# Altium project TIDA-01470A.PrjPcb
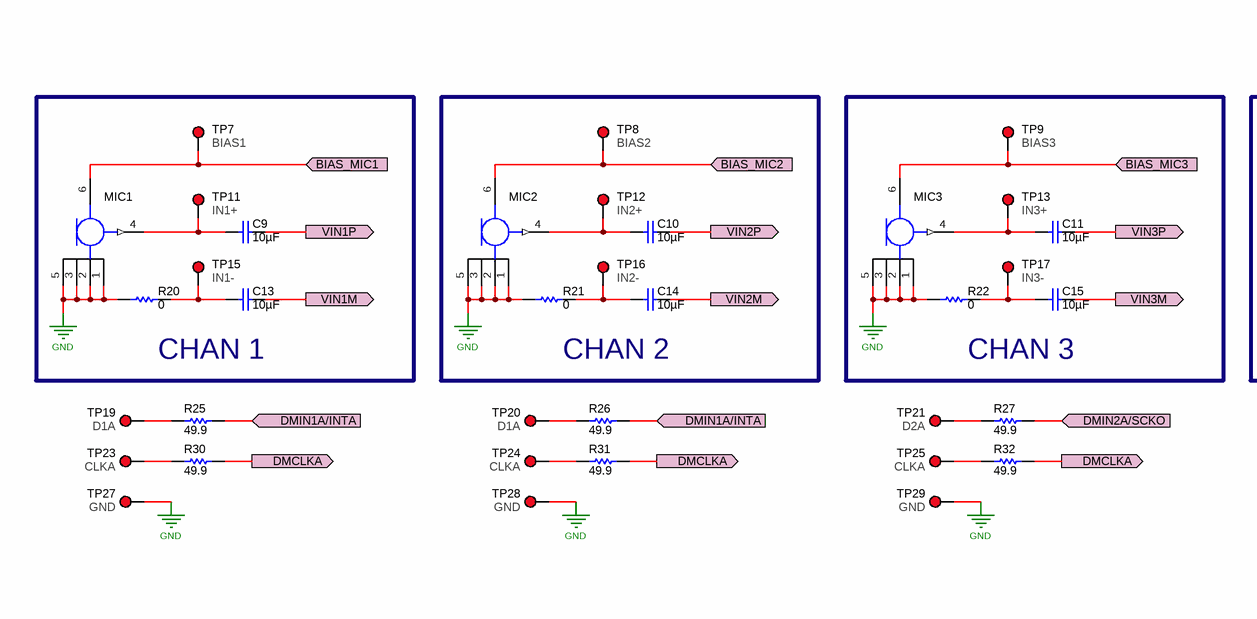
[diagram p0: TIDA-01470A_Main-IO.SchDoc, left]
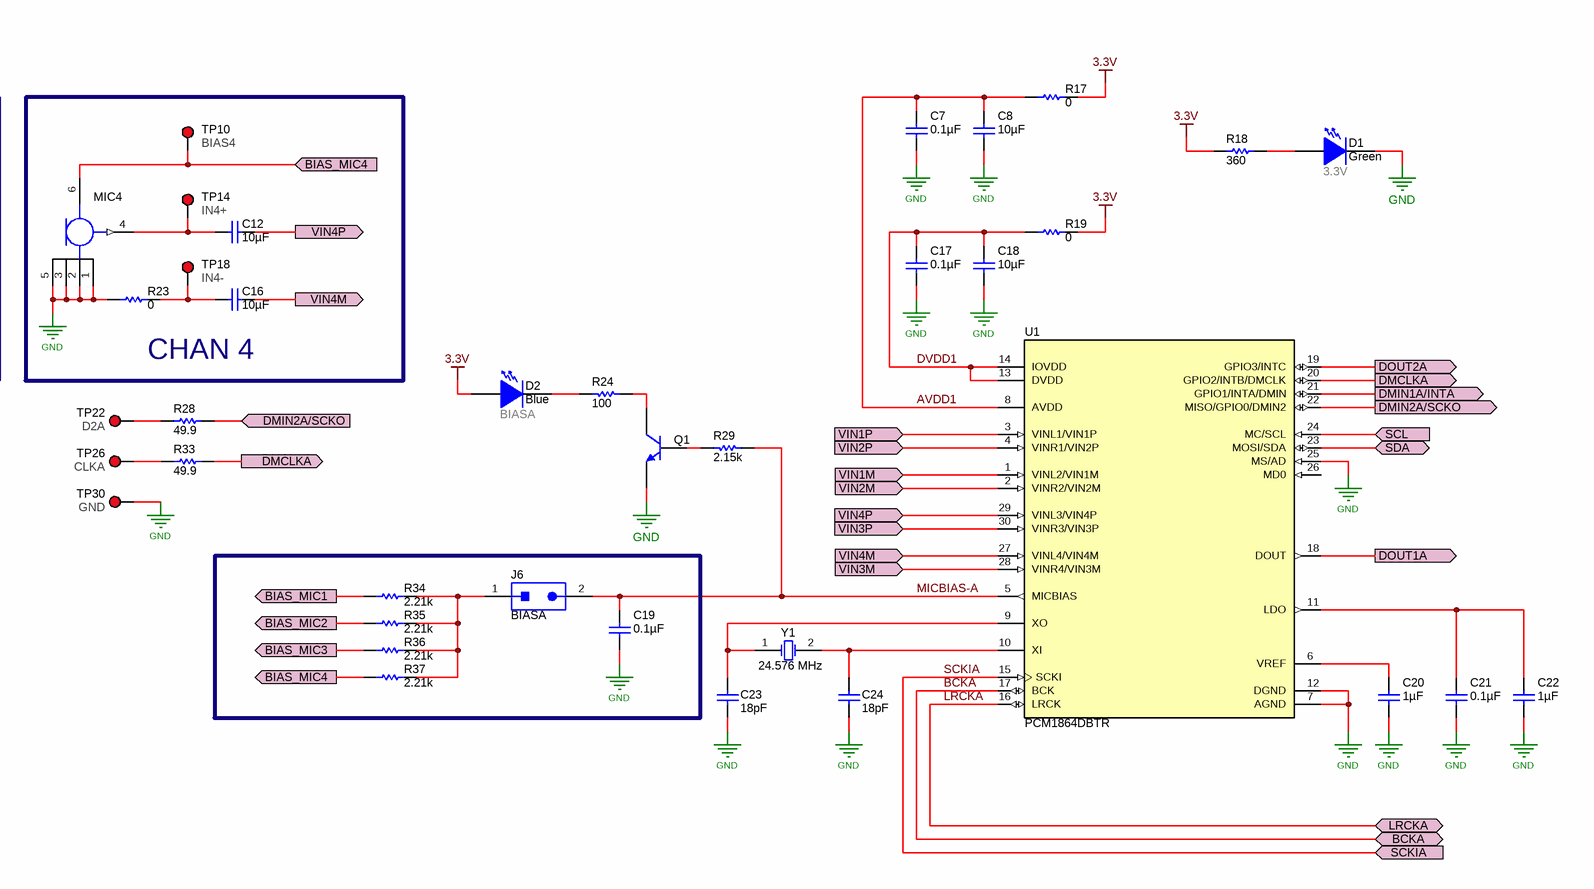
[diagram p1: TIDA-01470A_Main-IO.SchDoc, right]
CopyrightYear: 2017; EVM_Orderable: PCM1864LMBEVM; PCB_Layout: LDN; PCB_Rev: A; PRJ_Customer: Public Release; PRJ_Engineer: Ravi Patil; PRJ_Number: TIDA-01470; PRJ_Title: PCM1864 Linear Microphone Board Reference Design; SCH_Rev: A; TechSupport: http://www.ti.com/support; TID: 01470
3 sheets, 133 parts. Net scope: flat (ports and power ports of the same name join across sheets).
Board file: TIDA-01470A-PCB.PcbDoc
Sheets:
  TIDA-01470A_Main-IO.SchDoc
  TIDA-01470A_DIG-IO.SchDoc
  TIDA-01470A_Hardware.SchDoc

## Sheet TIDA-01470A_Main-IO.SchDoc: Main I/O
size 538 x 342 mm; Date: Not shown in title block; ApprovedBy: Not shown in title block; CheckedBy: Not shown in title block; Author: Not shown in title block; CompanyName: Not shown in title block; DrawnBy: LDN; Engineer: Not shown in title block; Organization: Not shown in title block; Address1: Not shown in title block; Address2: Not shown in title block; Address3: Not shown in title block; Address4: Not shown in title block; DocumentNumber: 1; Revision: Use project parameter SCH_Rev; SheetNumber: 1; SheetTotal: 3; PageSetup: Record=PageOptions¦CenterHorizontal=True¦CenterVertical=True¦PrintScale=1.00¦XCorrection=1.00¦YCorrection=1.00¦PrintKind=0¦BorderSize=5000000¦LeftOffset=0¦BottomOffset=0¦Orientation=2¦PaperLength=1000¦PaperWidth=1000¦Scale=100¦PaperSource=15¦PrintQuality=600¦MediaType=1¦DitherType=10¦PaperKind=Letter¦PrintScaleMode=1

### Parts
C7  ValueDisplayed: 0.1µF  [0603L]  (hidden comment: GRM188R71C104KA01D)
C8  ValueDisplayed: 10µF  [0805_KTR]  (hidden comment: GRM21BR71A106KE51K)
C9  ValueDisplayed: 10µF  [0805_KTR]  (hidden comment: GRM21BR71A106KE51K)
C10  ValueDisplayed: 10µF  [0805_KTR]  (hidden comment: GRM21BR71A106KE51K)
C11  ValueDisplayed: 10µF  [0805_KTR]  (hidden comment: GRM21BR71A106KE51K)
C12  ValueDisplayed: 10µF  [0805_KTR]  (hidden comment: GRM21BR71A106KE51K)
C13  ValueDisplayed: 10µF  [0805_KTR]  (hidden comment: GRM21BR71A106KE51K)
C14  ValueDisplayed: 10µF  [0805_KTR]  (hidden comment: GRM21BR71A106KE51K)
C15  ValueDisplayed: 10µF  [0805_KTR]  (hidden comment: GRM21BR71A106KE51K)
C16  ValueDisplayed: 10µF  [0805_KTR]  (hidden comment: GRM21BR71A106KE51K)
C17  ValueDisplayed: 0.1µF  [0603L]  (hidden comment: GRM188R71C104KA01D)
C18  ValueDisplayed: 10µF  [0805_KTR]  (hidden comment: GRM21BR71A106KE51K)
C19  ValueDisplayed: 0.1µF  [0603L]  (hidden comment: GRM188R71C104KA01D)
C20  ValueDisplayed: 1µF  [0603L]  (hidden comment: GRM188R71C105KA12D)
C21  ValueDisplayed: 0.1µF  [0603L]  (hidden comment: GRM188R71C104KA01D)
C22  ValueDisplayed: 1µF  [0603L]  (hidden comment: GRM188R71C105KA12D)
C23  ValueDisplayed: 18pF  [0603L]  (hidden comment: GRM1885C1H180JA01D)
C24  ValueDisplayed: 18pF  [0603L]  (hidden comment: GRM1885C1H180JA01D)
D1  3.3V  value Green  [LED_LTST-C171]
D2  BIASA  value Blue  [LED_SMLP12_BLUE]
J6  BIASA  [Sullins_PBC02SAAN]
MIC1  SPH1642HT5H-1  [Knowles_SPH1642HT5H-1]  (value not drawn)
MIC2  SPH1642HT5H-1  [Knowles_SPH1642HT5H-1]  (value not drawn)
MIC3  SPH1642HT5H-1  [Knowles_SPH1642HT5H-1]  (value not drawn)
MIC4  SPH1642HT5H-1  [Knowles_SPH1642HT5H-1]  (value not drawn)
Q1  MMBT2222A  [SOT-23]  (value not drawn)
R17  ValueDisplayed: 0  [0603]  (hidden comment: CRCW06030000Z0EA)
R18  value 360  [0402L]  (hidden comment: CRCW0402360RJNED)
R19  ValueDisplayed: 0  [0603L]  (hidden comment: CRCW06030000Z0EA)
R20  ValueDisplayed: 0  [0603L]  (hidden comment: CRCW06030000Z0EA)
R21  ValueDisplayed: 0  [0603L]  (hidden comment: CRCW06030000Z0EA)
R22  ValueDisplayed: 0  [0603L]  (hidden comment: CRCW06030000Z0EA)
R23  ValueDisplayed: 0  [0603L]  (hidden comment: CRCW06030000Z0EA)
R24  ValueDisplayed: 100  [0402L]  (hidden comment: ERJ-2RKF1000X)
R25  ValueDisplayed: 49.9  [0402L]  (hidden comment: RC0402FR-0749R9L)
R26  ValueDisplayed: 49.9  [0402L]  (hidden comment: RC0402FR-0749R9L)
R27  ValueDisplayed: 49.9  [0402L]  (hidden comment: RC0402FR-0749R9L)
R28  ValueDisplayed: 49.9  [0402L]  (hidden comment: RC0402FR-0749R9L)
R29  ValueDisplayed: 2.15k  [0402L]  (hidden comment: CRCW04022K15FKED)
R30  ValueDisplayed: 49.9  [0402L]  (hidden comment: RC0402FR-0749R9L)
R31  ValueDisplayed: 49.9  [0402L]  (hidden comment: RC0402FR-0749R9L)
R32  ValueDisplayed: 49.9  [0402L]  (hidden comment: RC0402FR-0749R9L)
R33  ValueDisplayed: 49.9  [0402L]  (hidden comment: RC0402FR-0749R9L)
R34  ValueDisplayed: 2.21k  [0402L]  (hidden comment: CRCW04022K21FKED)
R35  ValueDisplayed: 2.21k  [0402L]  (hidden comment: CRCW04022K21FKED)
R36  ValueDisplayed: 2.21k  [0402L]  (hidden comment: CRCW04022K21FKED)
R37  ValueDisplayed: 2.21k  [0402L]  (hidden comment: CRCW04022K21FKED)
TP7  BIAS1  [TestPoint_50x30-TH]
TP8  BIAS2  [TestPoint_50x30-TH]
TP9  BIAS3  [TestPoint_50x30-TH]
TP10  BIAS4  [TestPoint_50x30-TH]
TP11  IN1+  [TestPoint_50x30-TH]
TP12  IN2+  [TestPoint_50x30-TH]
TP13  IN3+  [TestPoint_50x30-TH]
TP14  IN4+  [TestPoint_50x30-TH]
TP15  IN1-  [TestPoint_50x30-TH]
TP16  IN2-  [TestPoint_50x30-TH]
TP17  IN3-  [TestPoint_50x30-TH]
TP18  IN4-  [TestPoint_50x30-TH]
TP19  D1A  [TestPoint_50x30-TH]
TP20  D1A  [TestPoint_50x30-TH]
TP21  D2A  [TestPoint_50x30-TH]
TP22  D2A  [TestPoint_50x30-TH]
TP23  CLKA  [TestPoint_50x30-TH]
TP24  CLKA  [TestPoint_50x30-TH]
TP25  CLKA  [TestPoint_50x30-TH]
TP26  CLKA  [TestPoint_50x30-TH]
TP27  GND  [TestPoint_50x30-TH]
TP28  GND  [TestPoint_50x30-TH]
TP29  GND  [TestPoint_50x30-TH]
TP30  GND  [TestPoint_50x30-TH]
U1  PCM1864DBTR  [DBT0030A_N]
Y1  Frequency: 24.576 MHz  [TXC_9B]  (hidden comment: 9B-24.576MEEJ-B)

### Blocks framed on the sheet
CHAN 1: C9 C13 MIC1 R20 TP7 TP11 TP15
CHAN 2: C10 C14 MIC2 R21 TP8 TP12 TP16
CHAN 3: C11 C15 MIC3 R22 TP9 TP13 TP17
CHAN 4: C12 C16 MIC4 R23 TP10 TP14 TP18

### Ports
BCKA (bidir), BIAS_MIC1 (in), BIAS_MIC1 (out), BIAS_MIC2 (in), BIAS_MIC2 (out), BIAS_MIC3 (in), BIAS_MIC3 (out), BIAS_MIC4 (in), BIAS_MIC4 (out), DMCLKA (out), DMIN1A/INTA (in), DMIN1A/INTA (out), DMIN2A/SCKO (in), DMIN2A/SCKO (out), DOUT1A (out), DOUT2A (out), LRCKA (bidir), SCKIA (in), SCL (in), SDA (bidir), VIN1M (in), VIN1M (out), VIN1P (in), VIN1P (out), VIN2M (in), VIN2M (out), VIN2P (in), VIN2P (out), VIN3M (in), VIN3M (out), VIN3P (in), VIN3P (out), VIN4M (in), VIN4M (out), VIN4P (in), VIN4P (out)

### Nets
3.3V: D2.1(A) R17.1 R18.2 R19.1
GND: C7.1 C8.1 C17.1 C18.1 C19.1 C20.2 C21.1 C22.2 C23.2 C24.2 D1.2(K) MIC1.1(GND) MIC1.2(GND) MIC1.3(GND) MIC1.5(GND) MIC2.1(GND) MIC2.2(GND) MIC2.3(GND) MIC2.5(GND) MIC3.1(GND) MIC3.2(GND) MIC3.3(GND) MIC3.5(GND) MIC4.1(GND) MIC4.2(GND) MIC4.3(GND) MIC4.5(GND) Q1.2(E) R20.2 R21.2 R22.2 R23.2 TP27.1 TP28.1 TP29.1 TP30.1 U1.7(AGND) U1.12(DGND) U1.25(MS/AD)
AVDD1: C7.2 C8.2 R17.2 U1.8(AVDD)
BCKA: U1.17(BCK) ; port BCKA
BIAS_MIC1: MIC1.6(VDD) R34.2 TP7.1 ; port BIAS_MIC1
BIAS_MIC2: MIC2.6(VDD) R35.2 TP8.1 ; port BIAS_MIC2
BIAS_MIC3: MIC3.6(VDD) R36.2 TP9.1 ; port BIAS_MIC3
BIAS_MIC4: MIC4.6(VDD) R37.2 TP10.1 ; port BIAS_MIC4
DMCLKA: R30.1 R31.1 R32.1 R33.1 U1.20(GPIO2/INTB/DMCLK) ; port DMCLKA
DMIN1A/INTA: R25.1 R26.1 U1.21(GPIO1/INTA/DMIN) ; port DMIN1A/INTA
DMIN2A/SCKO: R27.1 R28.1 U1.22(MISO/GPIO0/DMIN2) ; port DMIN2A/SCKO
DOUT1A: U1.18(DOUT) ; port DOUT1A
DOUT2A: U1.19(GPIO3/INTC) ; port DOUT2A
DVDD1: C17.2 C18.2 R19.2 U1.13(DVDD) U1.14(IOVDD)
LRCKA: U1.16(LRCK) ; port LRCKA
MICBIAS-A: C19.2 J6.2 R29.2 U1.5(MICBIAS)
SCKIA: U1.15(SCKI) ; port SCKIA
SCL: U1.24(MC/SCL) ; port SCL
SDA: U1.23(MOSI/SDA) ; port SDA
VIN1M: C13.1 U1.1(VINL2/VIN1M) ; port VIN1M
VIN1P: C9.1 U1.3(VINL1/VIN1P) ; port VIN1P
VIN2M: C14.1 U1.2(VINR2/VIN2M) ; port VIN2M
VIN2P: C10.1 U1.4(VINR1/VIN2P) ; port VIN2P
VIN3M: C15.1 U1.28(VINR4/VIN3M) ; port VIN3M
VIN3P: C11.1 U1.30(VINR3/VIN3P) ; port VIN3P
VIN4M: C16.1 U1.27(VINL4/VIN4M) ; port VIN4M
VIN4P: C12.1 U1.29(VINL3/VIN4P) ; port VIN4P
NetC9_2: C9.2 MIC1.4(OUTPUT) TP11.1
NetC10_2: C10.2 MIC2.4(OUTPUT) TP12.1
NetC11_2: C11.2 MIC3.4(OUTPUT) TP13.1
NetC12_2: C12.2 MIC4.4(OUTPUT) TP14.1
NetC13_2: C13.2 R20.1 TP15.1
NetC14_2: C14.2 R21.1 TP16.1
NetC15_2: C15.2 R22.1 TP17.1
NetC16_2: C16.2 R23.1 TP18.1
NetC20_1: C20.1 U1.6(VREF)
NetC21_2: C21.2 C22.1 U1.11(LDO)
NetC23_1: C23.1 U1.9(XO) Y1.1(OSC1)
NetC24_1: C24.1 U1.10(XI) Y1.2(OSC2)
NetD1_1: D1.1(A) R18.1
NetD2_2: D2.2(K) R24.1
NetJ6_1: J6.1 R34.1 R35.1 R36.1 R37.1
NetQ1_1: Q1.1(B) R29.1
NetQ1_3: Q1.3(C) R24.2
NetR25_2: R25.2 TP19.1
NetR26_2: R26.2 TP20.1
NetR27_2: R27.2 TP21.1
NetR28_2: R28.2 TP22.1
NetR30_2: R30.2 TP23.1
NetR31_2: R31.2 TP24.1
NetR32_2: R32.2 TP25.1
NetR33_2: R33.2 TP26.1

Not connected (* = marked no-connect by the designer): U1 26(MD0)

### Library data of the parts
C7 C17 C19 C21 = GRM188R71C104KA01D: CAP, CERM, 0.1 µF, 16 V, +/- 10%, X7R, 0603; Manufacturer: MuRata; Polarized: N; CompType: Capacitor; Value: 0.1uF; U/M: EA; Cap_F: 0.0000001; Tolerance_%: 10; Value1: Unknown; VDC_V: 16; Value2: 16V; TaMin_C: -55; TaMax_C: 125; Cap_Case: 0603; SizeArea_mm2: 1.28; SizeAreaWB_mm2: 4.68; SizeX_mm: 1.6; SizeY_mm: 0.8; SizeZ_mm: 1; AEC Category: Q200
C8-C16 C18 = GRM21BR71A106KE51K: CAP, CERM, 10 µF, 10 V, +/- 10%, X7R, 0805; Manufacturer: MuRata; Polarized: N; CompType: Capacitor; Value: 10uF; U/M: EA; Cap_F: 0.00001; Tolerance_%: 10; Value1: Unknown; Value2: 10V; TaMin_C: -55; TaMax_C: 125; Cap_Case: 0805; SizeArea_mm2: 2.5; SizeAreaWB_mm2: 6.75; SizeX_mm: 2; SizeY_mm: 1.25; SizeZ_mm: 1.45; AEC Category: Q200
C20 C22 = GRM188R71C105KA12D: CAP, CERM, 1 µF, 16 V, +/- 10%, X7R, 0603; Manufacturer: MuRata; Polarized: N; CompType: Capacitor; Value: 1uF; U/M: EA; Cap_F: 0.000001; Tolerance_%: 10; ESR_ohm: 0.011; Value1: 0.011 ohm; VDC_V: 16; Value2: 16V; TaMin_C: -55; TaMax_C: 125; Cap_Case: 0603; SizeArea_mm2: 1.28; SizeAreaWB_mm2: 4.68; SizeX_mm: 1.6; SizeY_mm: 0.8; SizeZ_mm: 1; AEC Category: Q200
C23 C24 = GRM1885C1H180JA01D: CAP, CERM, 18 pF, 50 V, +/- 5%, C0G/NP0, 0603; Manufacturer: MuRata; Polarized: N; CompType: Capacitor; Value: 18pF; U/M: EA; Cap_F: 0.000000000018; Tolerance_%: 5; Value1: Unknown; VDC_V: 50; Value2: 50V; TaMin_C: -55; TaMax_C: 125; Cap_Case: 0603; SizeArea_mm2: 1.28; SizeAreaWB_mm2: 4.68; SizeX_mm: 1.6; SizeY_mm: 0.8; SizeZ_mm: 1; AEC Category: Q200
D1 = LTST-C171GKT: LED, Green, SMD; Manufacturer: Lite-On; Type: AlInGaP; Vf_V: 2.1; Value2: 2.1V; Io_A: 20; Value1: W; U/M: EA
D2 = SMLP12BC7TT86: LED, Blue, SMD; Manufacturer: Rohm; Type: InGaN; Vf_V: 2.9; Value2: 2.9V; Io_A: 0.005; Tjmax_C: 85; Value1: W; U/M: EA
J6 = PBC02SAAN: Header, 100mil, 2x1, Gold, TH; Manufacturer: Sullins Connector Solutions; SymbolCreator: a0412235; Pitch_mm: 2.54; Gender: Male; Shrouded: N; Row_Count: 1; Current_A: 3; Voltage_V: 1800; Cert_UL: Y
MIC1-MIC4 = SPH1642HT5H-1: Wide Bandwidth, Low Noise, Precision Top Port SiSonic Microphone, SMD; Manufacturer: Knowles Accoustics; SymbolCreator: Altium
Q1 = MMBT2222A, Fairchild Semiconductor: Transistor, NPN, 40 V, 0.15 A, SOT-23; CompType: BJT; PNP: 0; NPN: 1; Vceo_V: 40; Vcesat1_V: 0.3; Value: 40 V; IcRated_A: 0.15; Value1: 0.15 A; HfeMax: 300; TaMin_C: -55; TaMax_C: 150; U/M: EA; AEC Category: Q101
R17 R19-R23 = CRCW06030000Z0EA: RES, 0, 5%, 0.1 W, 0603; Manufacturer: Vishay-Dale; CompType: Resistor; Value: 0; Value_Code: 0000; Tolerance_%: 5; Power_W: 0.1; Value2: 0.1W; VDC_V: 75; TempCo: 200 ppm/C; SizeArea_mm2: 1.28; SizeX_mm: 1.6; SizeY_mm: 0.8; SizeZ_mm: 1; EIA_Code: E24; U/M: EA; AEC Category: Q200
R18 = CRCW0402360RJNED: RES, 360, 5%, 0.063 W, 0402; Manufacturer: Vishay-Dale; CompType: Resistor; Value_Code: 360R; Tolerance_%: 5; Power_W: 0.063; Value2: 0.063W; VDC_V: 50; TempCo: 200 ppm/C; EIA_Code: E24; U/M: EA; AEC Category: Q200
R24 = ERJ-2RKF1000X: RES, 100, 1%, 0.1 W, 0402; Manufacturer: Panasonic; CompType: Resistor; Value: 100; Value_Code: 100R; Tolerance_%: 1; Power_W: 0.1; Value2: 0.1W; VDC_V: 50; TempCo: 100 ppm/C; EIA_Code: E96; U/M: EA; AEC Category: Q200; SizeArea_mm2: 0.5; SizeZ_mm: 0.6
R25-R28 R30-R33 = RC0402FR-0749R9L: RES, 49.9, 1%, 0.063 W, 0402; Manufacturer: Yageo America; CompType: Resistor; Value: 49.9; Value_Code: 49R9; Tolerance_%: 1; Power_W: 0.063; Value2: 0.063W; VDC_V: 50; TempCo: 100 ppm/C; SizeArea_mm2: 0.5; SizeZ_mm: 0.6; EIA_Code: E96; U/M: EA; AEC Category: Q200; AEC Qualified: N
R29 = CRCW04022K15FKED: RES, 2.15 k, 1%, 0.063 W, 0402; Manufacturer: Vishay-Dale; CompType: Resistor; Value: 2.15k; Res_ohm: 2150; Value_Code: 2k15; Tolerance_%: 1; Power_W: 0.063; Value2: 0.063W; VDC_V: 50; TempCo: 100 ppm/C; EIA_Code: E96; U/M: EA; AEC Category: Q200; SizeArea_mm2: 0.5; SizeZ_mm: 0.6
R34-R37 = CRCW04022K21FKED: RES, 2.21 k, 1%, 0.063 W, 0402; Manufacturer: Vishay-Dale; CompType: Resistor; Value: 2.21k; Res_ohm: 2210; Value_Code: 2k21; Tolerance_%: 1; Power_W: 0.063; Value2: 0.063W; VDC_V: 50; TempCo: 100 ppm/C; SizeArea_mm2: 0.5; SizeZ_mm: 0.6; EIA_Code: E96; U/M: EA; AEC Category: Q200
TP7-TP30 = 5000: Test Point, Miniature, Red, TH; Manufacturer: Keystone; CompType: Test Point Loop; ContactFinish: Silver
U1 = PCM1864DBTR: Universal Microphone to 2VRMS Analog input, 24-Bit, 192 kHz Stereo Front-End, DBT0030A; Manufacturer: Texas Instruments; SymbolCreator: Altium; SizeArea_mm2: 49.92; SizeAreaWB_mm2: 82.32; SizeX_mm: 6.4; SizeY_mm: 7.8; SizeZ_mm: 1.2; CompType: IC; U/M: EA
Y1 = 9B-24.576MEEJ-B: Crystal, 24.576MHz, 18 pF, TH; Manufacturer: TXC Corporation; SymbolCreator: a0412235; SizeAreaWB_mm2: 94.5; SizeArea_mm2: 57.5; SizeX_mm: 11.5; SizeY_mm: 5; SizeZ_mm: 3.68; U/M: EA; TaMin_C: -20; TaMax_C: 70; Frequency Stability: ±10ppm

## Sheet TIDA-01470A_DIG-IO.SchDoc: DIGITAL I/O
size 431 x 279 mm; Date: Not shown in title block; ApprovedBy: Not shown in title block; CheckedBy: Not shown in title block; Author: Not shown in title block; CompanyName: Not shown in title block; DrawnBy: LDN; Engineer: Not shown in title block; Organization: Not shown in title block; Address1: Not shown in title block; Address2: Not shown in title block; Address3: Not shown in title block; Address4: Not shown in title block; DocumentNumber: 2; Revision: Use project parameter SCH_Rev; SheetNumber: 2; SheetTotal: 3; PageSetup: Record=PageOptions¦CenterHorizontal=True¦CenterVertical=True¦PrintScale=1.00¦XCorrection=1.00¦YCorrection=1.00¦PrintKind=0¦BorderSize=5000000¦LeftOffset=0¦BottomOffset=0¦Orientation=2¦PaperLength=1000¦PaperWidth=1000¦Scale=100¦PaperSource=15¦PrintQuality=600¦MediaType=1¦DitherType=10¦PaperKind=Letter¦PrintScaleMode=1
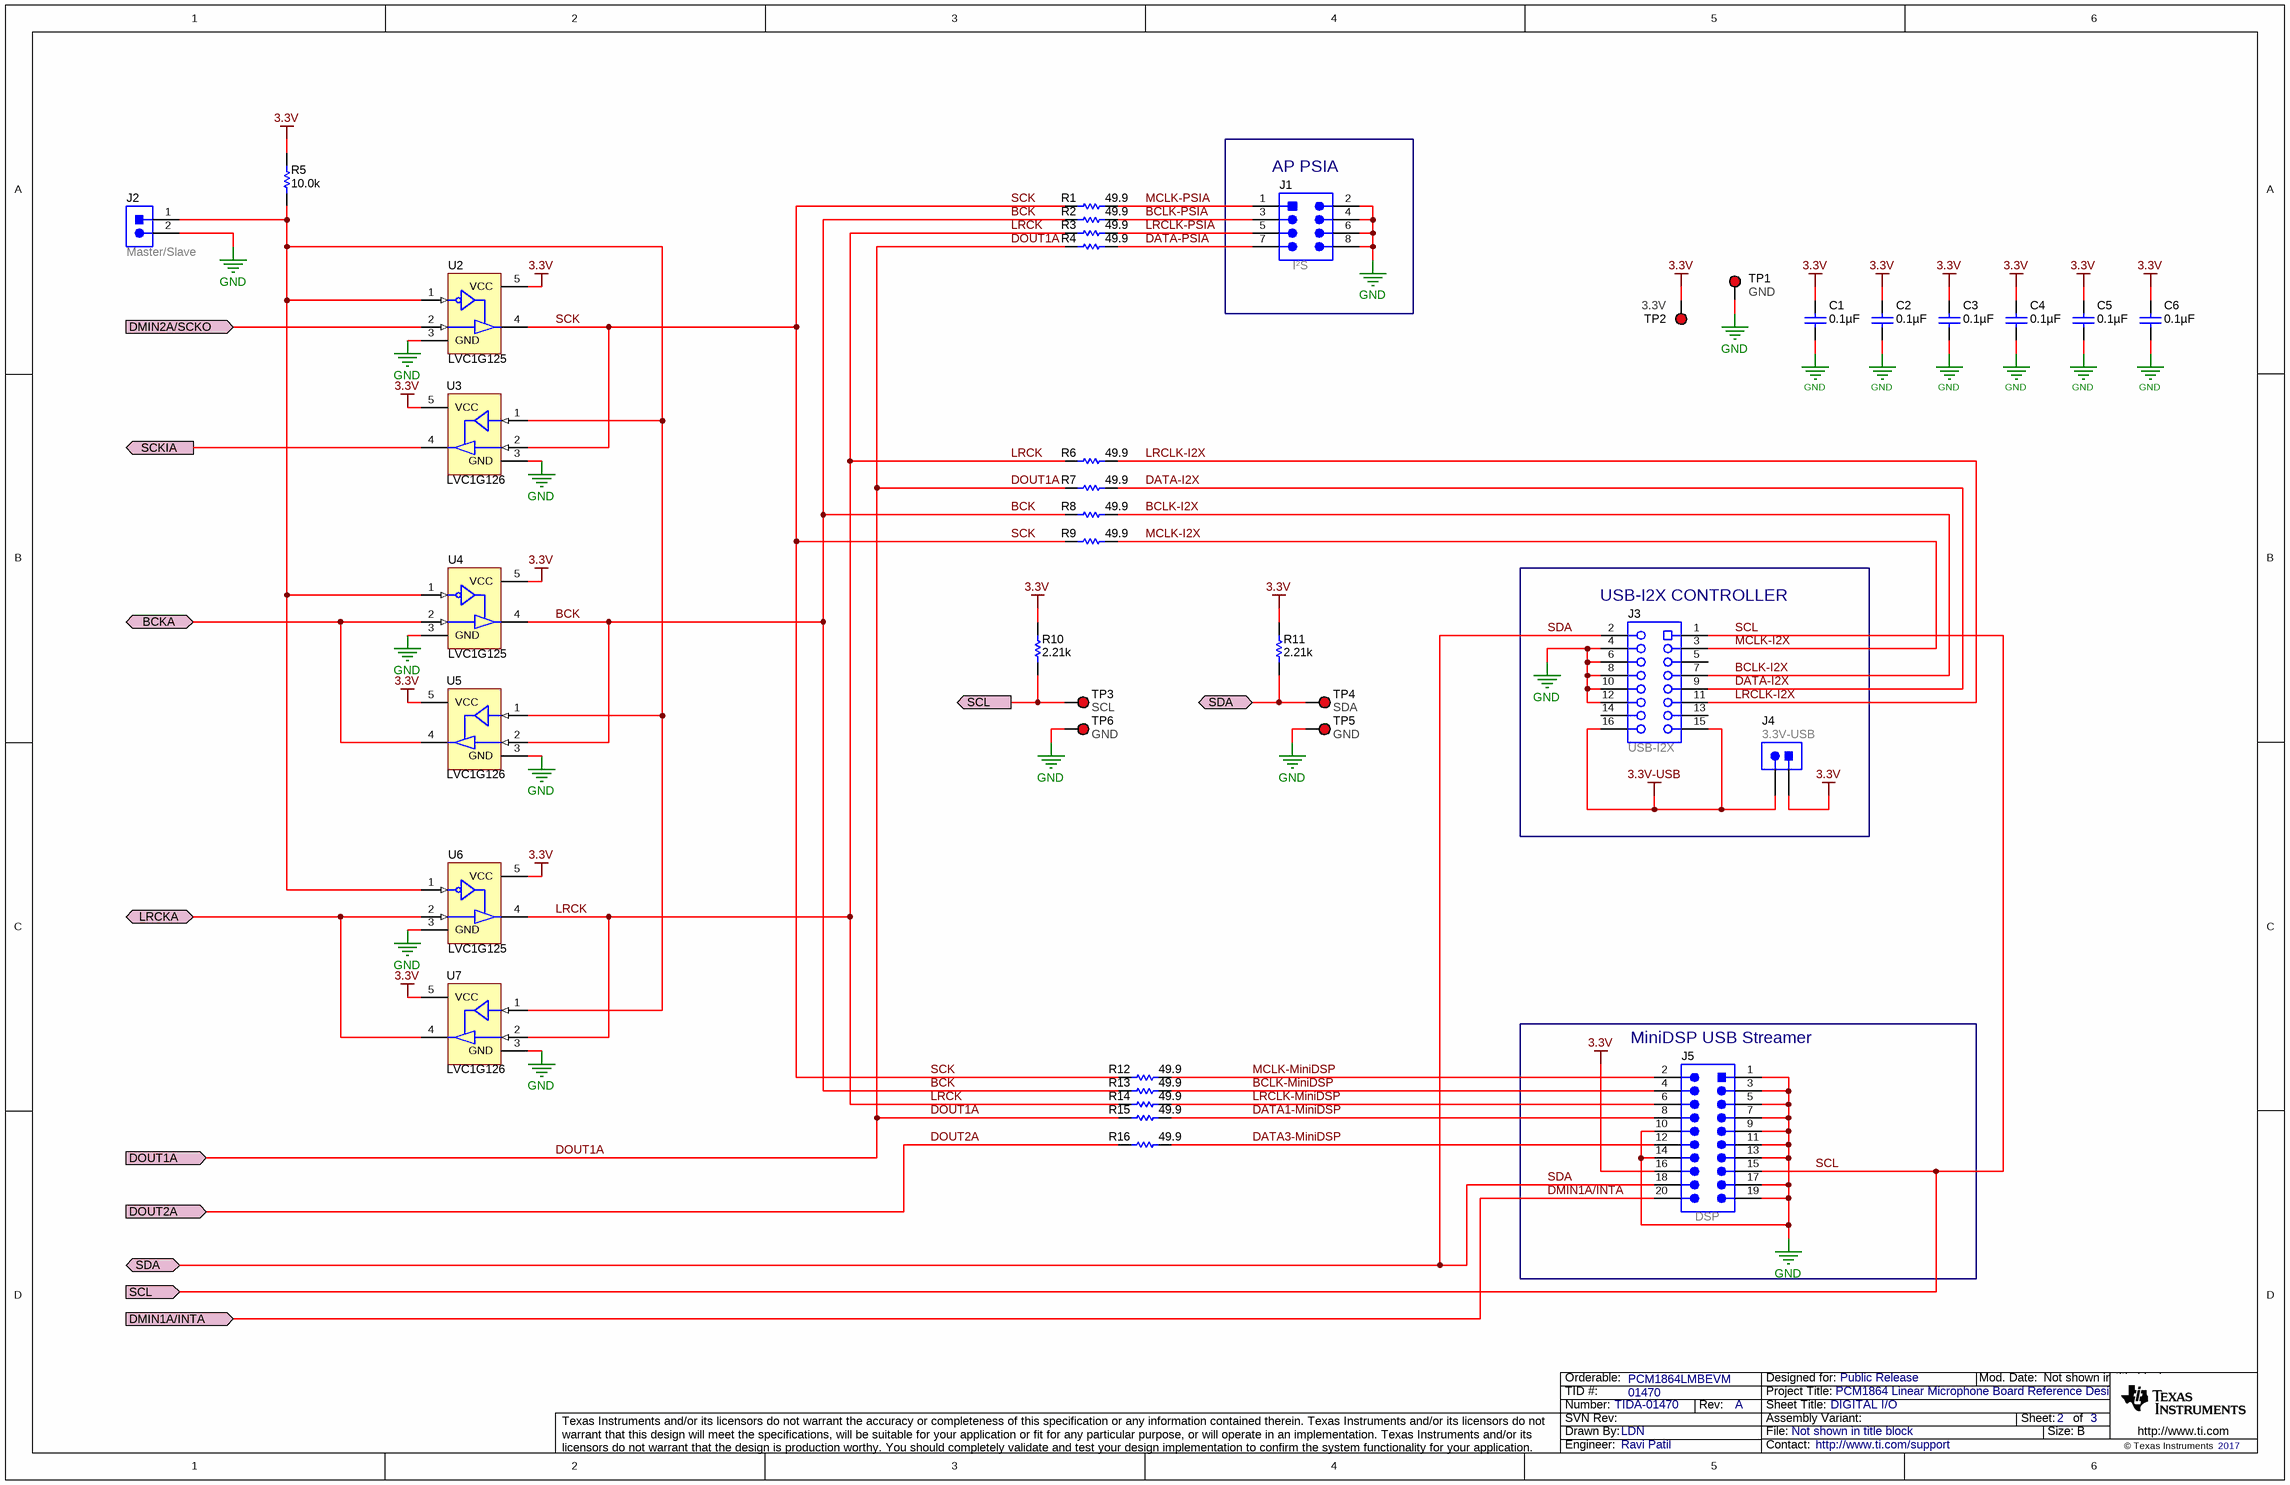
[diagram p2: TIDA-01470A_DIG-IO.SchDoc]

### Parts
C1  ValueDisplayed: 0.1µF  [0603L]  (hidden comment: GRM188R71C104KA01D)
C2  ValueDisplayed: 0.1µF  [0603L]  (hidden comment: GRM188R71C104KA01D)
C3  ValueDisplayed: 0.1µF  [0603L]  (hidden comment: GRM188R71C104KA01D)
C4  ValueDisplayed: 0.1µF  [0603L]  (hidden comment: GRM188R71C104KA01D)
C5  ValueDisplayed: 0.1µF  [0603L]  (hidden comment: GRM188R71C104KA01D)
C6  ValueDisplayed: 0.1µF  [0603L]  (hidden comment: GRM188R71C104KA01D)
J1  I²S  [CONN_PEC04DAAN]
J2  Master/Slave  [Sullins_PBC02SAAN]
J3  USB-I2X  [Sullins_PPPC082LJBN-RC]
J4  3.3V-USB  [Sullins_PBC02SAAN]
J5  DSP  [TSW-110-07-G-D]
R1  ValueDisplayed: 49.9  [0402L]  (hidden comment: RC0402FR-0749R9L)
R2  ValueDisplayed: 49.9  [0402L]  (hidden comment: RC0402FR-0749R9L)
R3  ValueDisplayed: 49.9  [0402L]  (hidden comment: RC0402FR-0749R9L)
R4  ValueDisplayed: 49.9  [0402L]  (hidden comment: RC0402FR-0749R9L)
R5  ValueDisplayed: 10.0k  [0603L]  (hidden comment: ERJ-3EKF1002V)
R6  ValueDisplayed: 49.9  [0402L]  (hidden comment: RC0402FR-0749R9L)
R7  ValueDisplayed: 49.9  [0402L]  (hidden comment: RC0402FR-0749R9L)
R8  ValueDisplayed: 49.9  [0402L]  (hidden comment: RC0402FR-0749R9L)
R9  ValueDisplayed: 49.9  [0402L]  (hidden comment: RC0402FR-0749R9L)
R10  ValueDisplayed: 2.21k  [0402L]  (hidden comment: CRCW04022K21FKED)
R11  ValueDisplayed: 2.21k  [0402L]  (hidden comment: CRCW04022K21FKED)
R12  ValueDisplayed: 49.9  [0402L]  (hidden comment: RC0402FR-0749R9L)
R13  ValueDisplayed: 49.9  [0402L]  (hidden comment: RC0402FR-0749R9L)
R14  ValueDisplayed: 49.9  [0402L]  (hidden comment: RC0402FR-0749R9L)
R15  ValueDisplayed: 49.9  [0402L]  (hidden comment: RC0402FR-0749R9L)
R16  ValueDisplayed: 49.9  [0402L]  (hidden comment: RC0402FR-0749R9L)
TP1  GND  [TestPoint_50x20-TH]
TP2  3.3V  [TestPoint_50x20-TH]
TP3  SCL  [TestPoint_50x30-TH]
TP4  SDA  [TestPoint_50x30-TH]
TP5  GND  [TestPoint_50x30-TH]
TP6  GND  [TestPoint_50x30-TH]
U2  LVC1G125  [DCK0005A_N]
U3  LVC1G126  [DCK0005A_N]
U4  LVC1G125  [DCK0005A_N]
U5  LVC1G126  [DCK0005A_N]
U6  LVC1G125  [DCK0005A_N]
U7  LVC1G126  [DCK0005A_N]

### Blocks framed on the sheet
AP PSIA: J1
USB-I2X CONTROLLER: J3 J4
MiniDSP USB Streamer: J5

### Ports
BCKA (bidir), DMIN1A/INTA (in), DMIN2A/SCKO (in), DOUT1A (in), DOUT2A (in), LRCKA (bidir), SCKIA (out), SCL (in), SCL (out), SDA (bidir)

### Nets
3.3V: C1.2 C2.2 C3.2 C4.2 C5.2 C6.2 J4.1 J5.16 R5.2 R10.1 R11.1 TP2.1 U2.5(VCC) U3.5(VCC) U4.5(VCC) U5.5(VCC) U6.5(VCC) U7.5(VCC)
3.3V-USB: J3.15 J3.16 J4.2
GND: C1.1 C2.1 C3.1 C4.1 C5.1 C6.1 J1.2 J1.4 J1.6 J1.8 J2.2 J3.4 J3.6 J3.8 J3.10 J3.12 J5.1 J5.3 J5.5 J5.7 J5.9 J5.10 J5.11 J5.13 J5.14 J5.17 J5.19 TP1.1 TP5.1 TP6.1 U2.3(GND) U3.3(GND) U4.3(GND) U5.3(GND) U6.3(GND) U7.3(GND)
BCK: R2.1 R8.1 R13.1 U4.4(Y) U5.2(A)
BCKA: U4.2(A) U5.4(Y) ; port BCKA
BCLK-I2X: J3.7 R8.2
BCLK-MiniDSP: J5.4 R13.2
BCLK-PSIA: J1.3 R2.2
DATA1-MiniDSP: J5.8 R15.2
DATA3-MiniDSP: J5.12 R16.2
DATA-I2X: J3.9 R7.2
DATA-PSIA: J1.7 R4.2
DMIN1A/INTA: J5.20 ; port DMIN1A/INTA
DMIN2A/SCKO: U2.2(A) ; port DMIN2A/SCKO
DOUT1A: R4.1 R7.1 R15.1 ; port DOUT1A
DOUT2A: R16.1 ; port DOUT2A
LRCK: R3.1 R6.1 R14.1 U6.4(Y) U7.2(A)
LRCKA: U6.2(A) U7.4(Y) ; port LRCKA
LRCLK-I2X: J3.11 R6.2
LRCLK-MiniDSP: J5.6 R14.2
LRCLK-PSIA: J1.5 R3.2
MCLK-I2X: J3.3 R9.2
MCLK-MiniDSP: J5.2 R12.2
MCLK-PSIA: J1.1 R1.2
SCK: R1.1 R9.1 R12.1 U2.4(Y) U3.2(A)
SCKIA: U3.4(Y) ; port SCKIA
SCL: J3.1 J5.15 R10.2 TP3.1 ; port SCL
SDA: J3.2 J5.18 R11.2 TP4.1 ; port SDA
NetJ2_1: J2.1 R5.1 U2.1(~{OE}) U3.1(~{OE}) U4.1(~{OE}) U5.1(~{OE}) U6.1(~{OE}) U7.1(~{OE})

Not connected (* = marked no-connect by the designer): J3 5 13 14

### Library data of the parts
C1-C6 = GRM188R71C104KA01D: as C7 on sheet TIDA-01470A_Main-IO
J1 = PEC04DAAN: Header, 100mil, 4x2, Tin, TH; Manufacturer: Sullins Connector Solutions; SymbolCreator: a0411947; Pitch_mm: 2.54; Gender: Male; Shrouded: N; Row_Count: 2; Current_A: 3; Voltage_V: 1800; Cert_UL: Y
J2 J4 = PBC02SAAN: as J6 on sheet TIDA-01470A_Main-IO
J3 = PPPC082LJBN-RC: Receptacle, 100mil, 8x2, Gold, R/A, TH; Manufacturer: Sullins Connector Solutions; SymbolCreator: a0411947
J5 = TSW-110-07-G-D: Header, 100mil, 10x2, Gold, TH; Manufacturer: Samtec; SymbolCreator: a0412235; Pitch_mm: 2.54; Gender: Male; Shrouded: N; Row_Count: 2; Current_A: 6.3; Voltage_V: 550; Cert_CSA: Y
R1-R4 R6-R9 R12-R16 = RC0402FR-0749R9L: as R25 on sheet TIDA-01470A_Main-IO
R5 = ERJ-3EKF1002V: RES, 10.0 k, 1%, 0.1 W, 0603; Manufacturer: Panasonic; CompType: Resistor; Value: 10.0k; Res_ohm: 10000; Value_Code: 10k0; Tolerance_%: 1; Power_W: 0.1; Value2: 0.1W; VDC_V: 75; TempCo: 100 ppm/C; SizeArea_mm2: 1.28; SizeX_mm: 1.6; SizeY_mm: 0.8; EIA_Code: E96; U/M: EA; AEC Category: Q200
R10 R11 = CRCW04022K21FKED: as R34 on sheet TIDA-01470A_Main-IO
TP1-TP6 = 5000: as TP7 on sheet TIDA-01470A_Main-IO
U2 U4 U6 = SN74LVC1G125DCKR: Single Bus Buffer Gate With 3-State Output, DCK0005A; Alternate PartNumber: SN74LVC1G125DCKT; Manufacturer: Texas Instruments; SymbolCreator: Altium; CompType: IC; U/M: EA
U3 U5 U7 = SN74LVC1G126DCKR: Single Bus Buffer Gate With 3-State Output, DCK0005A; Alternate PartNumber: SN74LVC1G126DCKT; Manufacturer: Texas Instruments; SymbolCreator: Altium; SizeArea_mm2: 4.2; SizeAreaWB_mm2: 9.3; SizeX_mm: 2.1; SizeY_mm: 2; SizeZ_mm: 1.1; CompType: IC; U/M: EA

## Sheet TIDA-01470A_Hardware.SchDoc
size Letter; Date: Not shown in title block; ApprovedBy: Not shown in title block; CheckedBy: Not shown in title block; Author: Not shown in title block; CompanyName: Not shown in title block; Engineer: Not shown in title block; Organization: Not shown in title block; Address1: Not shown in title block; Address2: Not shown in title block; Address3: Not shown in title block; Address4: Not shown in title block; DocumentNumber: 3; Revision: Use project parameter SCH_Rev; SheetNumber: 3; SheetTotal: 3; PageSetup: Record=PageOptions¦CenterHorizontal=True¦CenterVertical=True¦PrintScale=1.00¦XCorrection=1.00¦YCorrection=1.00¦PrintKind=0¦BorderSize=5000000¦LeftOffset=0¦BottomOffset=0¦Orientation=2¦PaperLength=1000¦PaperWidth=1000¦Scale=100¦PaperSource=15¦PrintQuality=600¦MediaType=1¦DitherType=10¦PaperKind=Letter¦PrintScaleMode=1
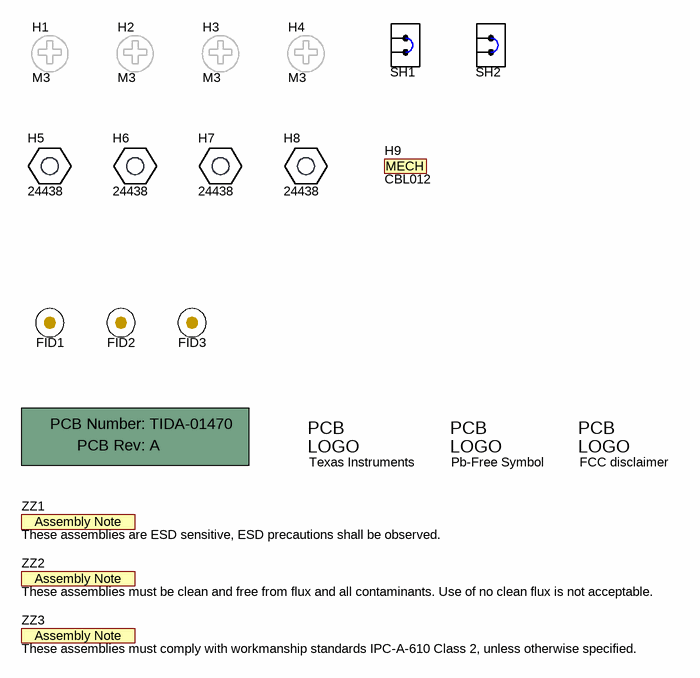
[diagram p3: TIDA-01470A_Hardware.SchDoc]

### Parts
!PCB  Printed Circuit Board  (value not drawn)  (mechanical)
FID1  Fiducial  [Fiducial10-20]  (value not drawn)
FID2  Fiducial  [Fiducial10-20]  (value not drawn)
FID3  Fiducial  [Fiducial10-20]  (value not drawn)
H1  M3  [BuildingFastener_MPMS_003_0005_PH]
H2  M3  [BuildingFastener_MPMS_003_0005_PH]
H3  M3  [BuildingFastener_MPMS_003_0005_PH]
H4  M3  [BuildingFastener_MPMS_003_0005_PH]
H5  24438  [Keystone24438]
H6  24438  [Keystone24438]
H7  24438  [Keystone24438]
H8  24438  [Keystone24438]
H9  CBL012  (mechanical)
Logo1  Texas Instruments  [TI_Stacked_Overlay_Small]  (no BOM)
Logo2  Pb-Free Symbol  [Pb-Free_Overlay_Small]  (no BOM)
Logo3  FCC disclaimer  [FCC_disclaimer_stacked]  (no BOM)
SH1  SNT-100-BK-G  [SNT-100-BK-G]  (value not drawn)
SH2  SNT-100-BK-G  [SNT-100-BK-G]  (value not drawn)
ZZ1  These assemblies are ESD sensitive, ESD precautions shall be observed.  [AssemblyNote]  (no BOM)
ZZ2  These assemblies must be clean and free from flux and all contaminants. Use of no clean flux is not acceptable.  [AssemblyNote]  (no BOM)
ZZ3  These assemblies must comply with workmanship standards IPC-A-610 Class 2, unless otherwise specified.  [AssemblyNote]  (no BOM)

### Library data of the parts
!PCB = PCB: Manufacturer: Any; PartNumber: TIDA-01470; SymbolCreator: a0412235
FID1-FID3 = Fiducial: Fiducial mark.  There is nothing to buy or mount.; SymbolCreator: codlsc
H1-H4 = MPMS 003 0005 PH: MACHINE SCREW PAN PHILLIPS M3 5mm; Manufacturer: B&F Fastener Supply; CompType: Hardware
H5-H8 = 24438: Standoff, Hex,25mm Length, M3, Aluminum; Manufacturer: Keystone; SymbolCreator: a0412235; CompType: Hardware
H9 = MechPart: CBL012 Cable Assembly; Manufacturer: Used in BOM report; SymbolCreator: codlsc; CompType: Mechanical; U/M: EA
Logo1 = TI_Logo: Texas Instrument Corporate Signature; SymbolCreator: codlsc
Logo2 = Pb-Free: SymbolCreator: a0412235
Logo3 = FCC_disclaimer: SymbolCreator: codlsc
SH1 SH2 = SNT-100-BK-G: Shunt, 100mil, Gold plated, Black; Manufacturer: Samtec; Alternate Manufacturer: 3M; Alternate PartNumber: 969102-0000-DA; Value: 1x2; Note: You can "mate" this to a header by matching the designator.  i.e. use SH-J3 for header J3
ZZ1-ZZ3 = AssemblyNote: SymbolCreator: codlsc

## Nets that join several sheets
3.3V: TIDA-01470A_Main-IO (D2.1 R17.1 R18.2 R19.1), TIDA-01470A_DIG-IO (18 pins)
GND: TIDA-01470A_Main-IO (39 pins), TIDA-01470A_DIG-IO (36 pins)
BCKA: TIDA-01470A_Main-IO (U1.17), TIDA-01470A_DIG-IO (U4.2 U5.4)
DMIN1A/INTA: TIDA-01470A_Main-IO (R25.1 R26.1 U1.21), TIDA-01470A_DIG-IO (J5.20)
DMIN2A/SCKO: TIDA-01470A_Main-IO (R27.1 R28.1 U1.22), TIDA-01470A_DIG-IO (U2.2)
DOUT1A: TIDA-01470A_Main-IO (U1.18), TIDA-01470A_DIG-IO (R4.1 R7.1 R15.1)
DOUT2A: TIDA-01470A_Main-IO (U1.19), TIDA-01470A_DIG-IO (R16.1)
LRCKA: TIDA-01470A_Main-IO (U1.16), TIDA-01470A_DIG-IO (U6.2 U7.4)
SCKIA: TIDA-01470A_Main-IO (U1.15), TIDA-01470A_DIG-IO (U3.4)
SCL: TIDA-01470A_Main-IO (U1.24), TIDA-01470A_DIG-IO (J3.1 J5.15 R10.2 TP3.1)
SDA: TIDA-01470A_Main-IO (U1.23), TIDA-01470A_DIG-IO (J3.2 J5.18 R11.2 TP4.1)

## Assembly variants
001: not fitted FID1 FID2 FID3 TP1 TP2 TP3 TP4 TP5 TP6 TP7 TP8 TP9 TP10 TP11 TP12 TP13 TP14 TP15 TP16 TP17 TP18 TP19 TP20 TP21 TP22 TP23 TP24 TP25 TP26 TP27 TP28 TP29 TP30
